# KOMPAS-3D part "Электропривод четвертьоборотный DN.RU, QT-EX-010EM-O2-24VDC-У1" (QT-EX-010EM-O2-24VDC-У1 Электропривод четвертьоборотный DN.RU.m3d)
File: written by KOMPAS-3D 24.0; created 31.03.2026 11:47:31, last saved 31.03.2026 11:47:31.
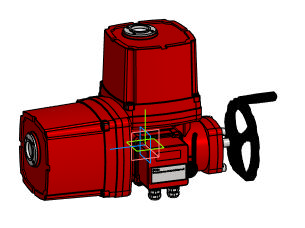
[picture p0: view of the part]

Document properties: Автор: DN.RU; Полное имя файла: D:\PROJECT CAD\DN.RU\...194\Исходники\QT-EX-010EM-O2-24VDC-У1\QT-EX-010EM-O2-24VDC-У1 Электропривод четвертьоборотный DN.RU.m3d

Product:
- Body: Твердое тело1  | qty 1
    Масса: 65.658095
- Part/product: Электропривод четвертьоборотный DN.RU  | designation QT-EX-010EM-O2-24VDC-У1
    Масса: 13
    Раздел спецификации: Прочие изделия
    Комментарий: D300-04900
    Примечание: D300-04900
    additional columns: Сталь

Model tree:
1. Твердое тело1  (labels: Твердое тело1)

Expressions: QT-EX-010EM-O2-24VDC-У1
